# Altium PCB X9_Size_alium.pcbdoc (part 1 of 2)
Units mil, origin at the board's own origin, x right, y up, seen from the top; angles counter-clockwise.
Board outline 3938 x 2560.05 mil, 2 copper layers (TOP, BOTTOM), stack 10.4 mil thick; 72 components, 121 nets, 447 pads, 520 vias.
Unrouted connection lines stored in the file: 78.
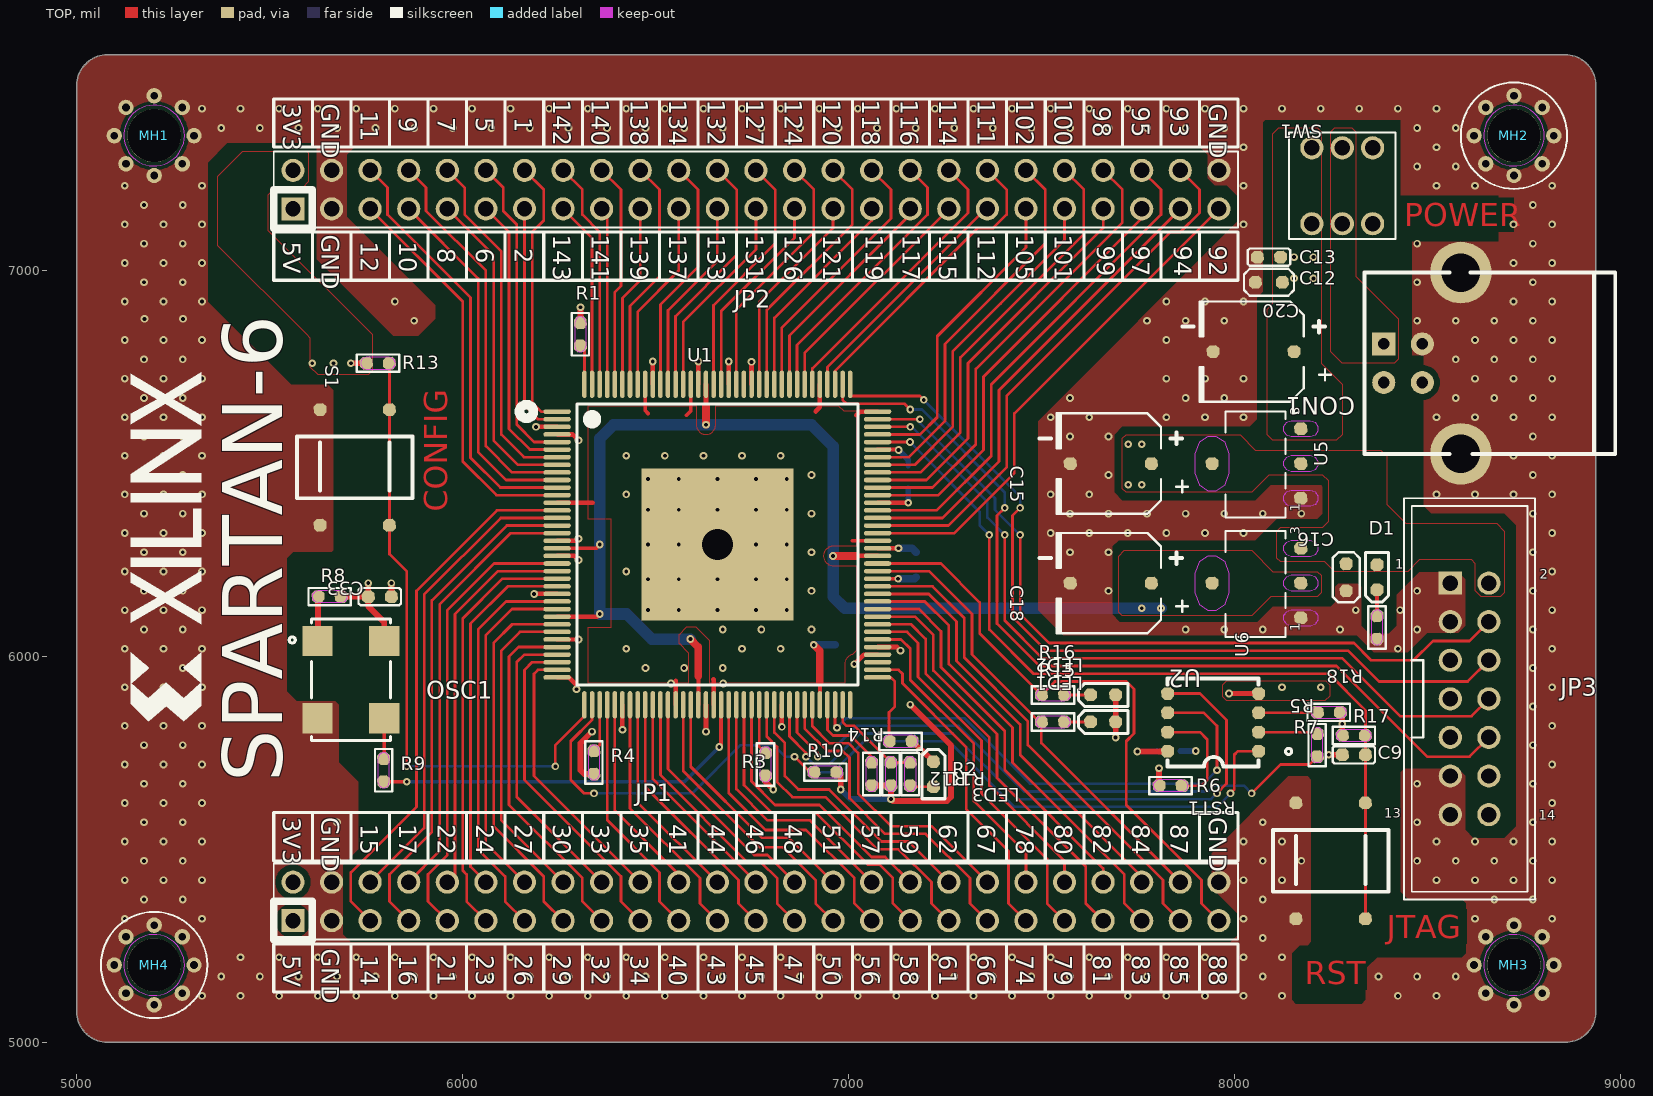
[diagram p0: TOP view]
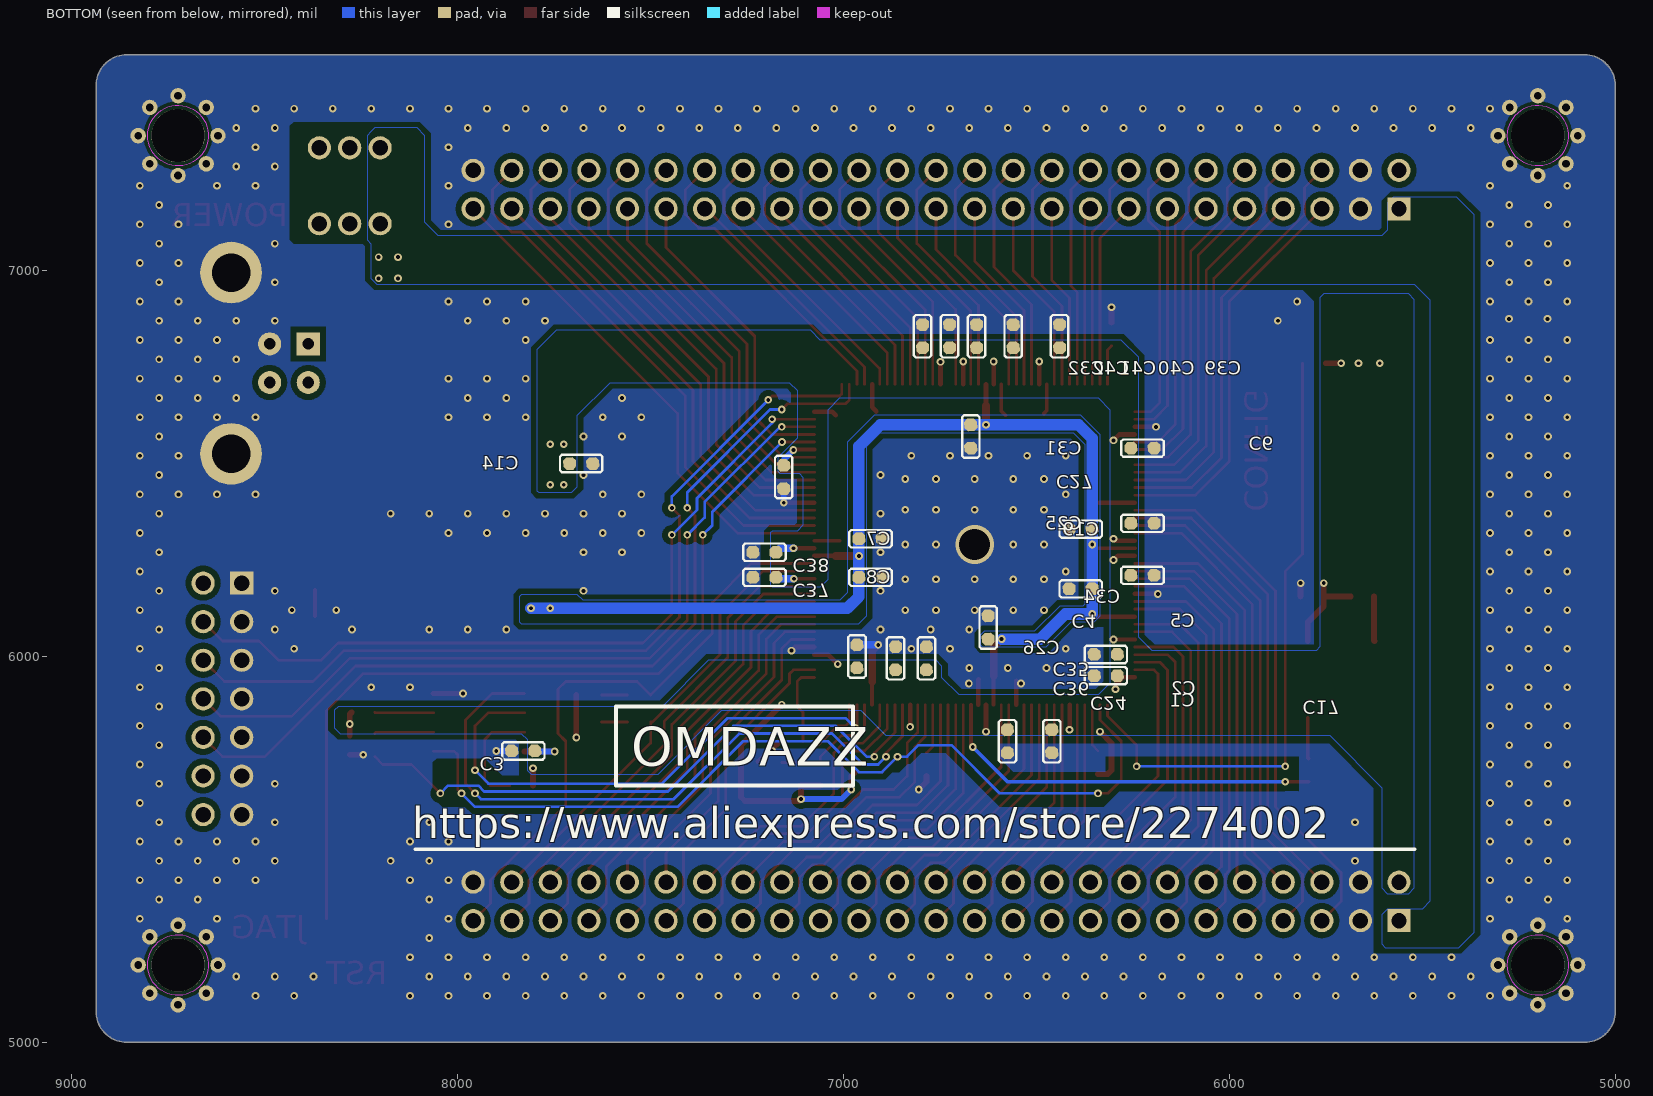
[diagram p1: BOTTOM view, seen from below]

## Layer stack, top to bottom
TOP: signal copper 1.2
Dielectric: core 8, FR-4, Dk 4.5
BOTTOM: signal copper 1.2

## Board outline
4999.5,5078.74 ccw(c5078.74,5078.74) 5078.74,4999.5 8858.26,4999.5 ccw(c8858.26,5078.74) 8937.5,5078.74 8937.5,7480.31 ccw(c8858.26,7480.31) 8858.26,7559.55 5078.74,7559.55 ccw(c5078.74,7480.31) 4999.5,7480.31

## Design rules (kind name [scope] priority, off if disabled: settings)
Clearance [All] p1: gap=10
PlaneConnect [All] p1: planeconnectstyle=Direct reliefexpansion=20 reliefentries=4 reliefconductorwidth=10 reliefairgap=10
PolygonConnect [All] p1: connectstyle=Direct reliefconductorwidth=10 reliefentries=4 polygonreliefangle="90 Angle"
RoutingVias [All] p1: holewidth=28 width=50 viastyle="Through Hole" minholewidth=28 minwidth=50 maxholewidth=28 maxwidth=50
SilkscreenOverComponentPads [All] p1: minsilkscreentomaskgap=10
SolderMaskExpansion [All] p1: expansion=4
TestPointUsage [All] p1: valid=0 allowmultiple=FALSE
Testpoint [All] p1: side=15 testpointundercomponent=TRUE minsize=40 maxsize=100 preferedsize=60 minholesize=0 maxholesize=40 preferedholesize=32 testpointgrid=1 style=1023 order=0-112345678
Width [All] p1: maxlimit=10 minlimit=10 preferedwidth=10 impedancedriven=TRUE minimp=60.000000 maximp=60.000000 favimp=60.000000
22 further rules are at their usual default settings.

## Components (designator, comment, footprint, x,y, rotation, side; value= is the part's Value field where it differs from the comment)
C1 "C0603" C0603#1 6575,5780 r90 bottom
C2 "C0603" C0603#1 6785,5995 r270 bottom
C3 "C0603" C0603#2 7830,5755 r0 bottom
C4 "C0603" C0603#2 6385,6175 r0 bottom
C5 "C0603" C0603#1 6625,6075 r90 bottom
C6 "C0603" C0603#1 6670,6570 r270 bottom
C7 "C0603" C0603#2 6930,6305 r180 bottom
C8 "C0603" C0603#2 6930,6205 r180 bottom
C9 "C0603" C0603#3 8310,5745 r0 top
C12 "C0805" C0805#1 8090,6970 r0 top
C13 "C0603" C0603#3 8090,7035 r0 top
C14 "C0603" C0603#2 7680,6500 r180 bottom
C15 "CE660X660H570" CE660X660H570 7680,6500 r180 top
C16 "C0805" C0805#2 8290,6205 r90 top
C17 "C0603" C0603#1 6460,5780 r270 bottom
C18 "CE660X660H570" CE660X660H570 7680,6190 r180 top
C19 "C0603" C0603#2 6385,6330 r180 bottom
C20 "CE660X660H570" CE660X660H570 8050,6790 r180 top
C24 "C0603" C0603#1 6865,5995 r90 bottom
C25 "C0603" C0603#2 6225,6345 r180 bottom
C26 "C0603" C0603#1 6965,6000 r90 bottom
C27 "C0603" C0603#1 7155,6465 r270 bottom
C31 "C0603" C0603#2 6225,6540 r180 bottom
C32 "C0603" C0603#1 6795,6830 r90 bottom
C33 "C0603" C0603#3 5785,6155 r180 top
C34 "C0603" C0603#2 6225,6210 r180 bottom
C35 "C0603" C0603#2 6320,6005 r0 bottom
C36 "C0603" C0603#2 6320,5950 r0 bottom
C37 "C0603" C0603#2 7205,6205 r0 bottom
C38 "C0603" C0603#2 7205,6270 r0 bottom
C39 "C0603" C0603#1 6440,6830 r90 bottom
C40 "C0603" C0603#1 6560,6830 r90 bottom
C41 "C0603" C0603#1 6655,6830 r90 bottom
C42 "C0603" C0603#1 6725,6830 r90 bottom
CON1 "USB_B_STD" USB_B_STD 8510,6760 r90 top
D1 "DIODE-0603" DIODE-0603#1 8370,6205 r270 top
JP1 "HD2X25-254_WYJ" HD2X25-254_WYJ 6760,5365 r0 top
JP2 "HD2X25-254_WYJ" HD2X25-254_WYJ 6760,7210 r0 top
JP3 "HD2X7-254_B" HD2X7-254_B 8610,5890 r270 top
LED1 "DIODE-0603" DIODE-0603#2 7660,5830 r180 top
LED2 "DIODE-0603" DIODE-0603#2 7660,5900 r180 top
LED3 "DIODE-0603" DIODE-0603#1 7220,5695 r90 top
MH1 "MH350P700_8" MH350P700_8 5200,7350 r0 top
MH2 "MH350P700_8" MH350P700_8 8725,7350 r0 top
MH3 "MH350P700_8" MH350P700_8 8725,5200 r0 top
MH4 "MH350P700_8" MH350P700_8 5200,5200 r0 top
OSC1 "OSC" OSC 5710,5940 r270 top
R1 "R0603" R0603#1 6305,6835 r270 top
R2 "R0603" R0603#1 7060,5695 r270 top
R3 "R0603" R0603#1 6785,5720 r270 top
R4 "R0603" R0603#1 6340,5725 r270 top
R5 "R0603" R0603#2 8245,5855 r180 top
R6 "R0603" R0603#2 7835,5665 r0 top
R7 "R0603" R0603#1 8215,5770 r270 top
R8 "R0603" R0603#2 5655,6155 r0 top
R9 "R0603" R0603#1 5795,5705 r270 top
R10 "R0603" R0603#2 6940,5700 r0 top
R11 "R0603" R0603#1 7160,5695 r90 top
R12 "R0603" R0603#1 7110,5695 r90 top
R13 "R0603" R0603#2 5780,6760 r0 top
R14 "R0603" R0603#2 7135,5780 r180 top
R15 "R0603" R0603#2 7530,5830 r0 top
R16 "R0603" R0603#2 7530,5900 r0 top
R17 "R0603" R0603#2 8310,5795 r0 top
R18 "R0603" R0603#1 8370,6075 r90 top
RST1 "KEY" KEY 8250,5470 r180 top
S1 "KEY" KEY 5720,6490 r180 top
SW1 "SWITCH2X3_700X700" SWITCH2X3_700X700 8280,7220 r180 top
U1 "EQFP144_EP59" EQFP144_EP59 6660,6290 r0 top
U2 "SO8" SO8 7945,5810 r180 top
U5 "SOT223_4" SOT223_4 8055,6500 r90 top
U6 "SOT223_4" SOT223_4 8055,6190 r90 top

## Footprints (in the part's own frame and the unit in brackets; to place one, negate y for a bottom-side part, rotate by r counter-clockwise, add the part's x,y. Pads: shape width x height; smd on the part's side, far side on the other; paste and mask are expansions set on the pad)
C0603#1 [mil] "C0603"
  oct 33.3x33.3 smd rot 93: 1(30,0) 2(-30,0)
  silkscreen extent -55,-23 55,23
C0603#2 [mil] "C0603"
  oct 33.3x33.3 smd rot 3: 1(30,0) 2(-30,0)
  silkscreen extent -55,-22 55,22
C0603#3 [mil] "C0603"
  oct 33.3x33.3 smd rot 3: 1(-30,0) 2(30,0)
  silkscreen extent -55,-22 55,22
C0805#1 [mil] "C0805"
  oct 33.3x33.3 smd rot 3: 1(-35,0) 2(35,0)
  silkscreen extent -65,-35 65,35
C0805#2 [mil] "C0805"
  oct 33.3x33.3 smd rot 93: 1(-35,0) 2(35,0)
  silkscreen extent -65,-35 65,35
CE660X660H570 [mil] "CE660X660H570"
  oct 33.3x33.3 smd rot 3: 1(-105,0) 2(105,0)
  silkscreen extent -200,-130 185,130
DIODE-0603#1 [mil] "DIODE-0603"
  oct 33.3x33.3 smd rot 93: A(-32.5,0) K(32.5,0)
  silkscreen extent -64,-30 64,30
DIODE-0603#2 [mil] "DIODE-0603"
  oct 33.3x33.3 smd rot 3: A(-32.5,0) K(32.5,0)
  silkscreen extent -64,-30 64,30
EQFP144_EP59 [mil] "EQFP144_EP59"
  oval 70.9x11.8 smd: 1(-415.4,344.5) 2(-415.4,324.8) 3(-415.4,305.1) 4(-415.4,285.4) 5(-415.4,265.7) 6(-415.4,246.1) 7(-415.4,226.4) 8(-415.4,206.7) 9(-415.4,187) 10(-415.4,167.3) 11(-415.4,147.6) 12(-415.4,128) 13(-415.4,108.3) 14(-415.4,88.6) 15(-415.4,68.9) 16(-415.4,49.2) 17(-415.4,29.5) 18(-415.4,9.8) 19(-415.4,-9.8) 20(-415.4,-29.5) 21(-415.4,-49.2) 22(-415.4,-68.9) 23(-415.4,-88.6) 24(-415.4,-108.3) 25(-415.4,-128) 26(-415.4,-147.6) 27(-415.4,-167.3) 28(-415.4,-187) 29(-415.4,-206.7) 30(-415.4,-226.4) 31(-415.4,-246.1) 32(-415.4,-265.7) 33(-415.4,-285.4) 34(-415.4,-305.1) 35(-415.4,-324.8) 36(-415.4,-344.5) 73(415.4,-344.5) 74(415.4,-324.8) 75(415.4,-305.1) 76(415.4,-285.4) 77(415.4,-265.7) 78(415.4,-246.1) 79(415.4,-226.4) 80(415.4,-206.7) 81(415.4,-187) 82(415.4,-167.3) 83(415.4,-147.6) 84(415.4,-128) 85(415.4,-108.3) 86(415.4,-88.6) 87(415.4,-68.9) 88(415.4,-49.2) 89(415.4,-29.5) 90(415.4,-9.8) 91(415.4,9.8) 92(415.4,29.5) 93(415.4,49.2) 94(415.4,68.9) 95(415.4,88.6) 96(415.4,108.3) 97(415.4,128) 98(415.4,147.6) 99(415.4,167.3) 100(415.4,187) 101(415.4,206.7) 102(415.4,226.4) 103(415.4,246.1) 104(415.4,265.7) 105(415.4,285.4) 106(415.4,305.1) 107(415.4,324.8) 108(415.4,344.5)
  oval 11.8x70.9 smd: 37(-344.5,-415.4) 38(-324.8,-415.4) 39(-305.1,-415.4) 40(-285.4,-415.4) 41(-265.7,-415.4) 42(-246.1,-415.4) 43(-226.4,-415.4) 44(-206.7,-415.4) 45(-187,-415.4) 46(-167.3,-415.4) 47(-147.6,-415.4) 48(-128,-415.4) 49(-108.3,-415.4) 50(-88.6,-415.4) 51(-68.9,-415.4) 52(-49.2,-415.4) 53(-29.5,-415.4) 54(-9.8,-415.4) 55(9.8,-415.4) 56(29.5,-415.4) 57(49.2,-415.4) 58(68.9,-415.4) 59(88.6,-415.4) 60(108.3,-415.4) 61(128,-415.4) 62(147.6,-415.4) 63(167.3,-415.4) 64(187,-415.4) 65(206.7,-415.4) 66(226.4,-415.4) 67(246.1,-415.4) 68(265.7,-415.4) 69(285.4,-415.4) 70(305.1,-415.4) 71(324.8,-415.4) 72(344.5,-415.4) 109(344.5,415.4) 110(324.8,415.4) 111(305.1,415.4) 112(285.4,415.4) 113(265.7,415.4) 114(246.1,415.4) 115(226.4,415.4) 116(206.7,415.4) 117(187,415.4) 118(167.3,415.4) 119(147.6,415.4) 120(128,415.4) 121(108.3,415.4) 122(88.6,415.4) 123(68.9,415.4) 124(49.2,415.4) 125(29.5,415.4) 126(9.8,415.4) 127(-9.8,415.4) 128(-29.5,415.4) 129(-49.2,415.4) 130(-68.9,415.4) 131(-88.6,415.4) 132(-108.3,415.4) 133(-128,415.4) 134(-147.6,415.4) 135(-167.3,415.4) 136(-187,415.4) 137(-206.7,415.4) 138(-226.4,415.4) 139(-246.1,415.4) 140(-265.7,415.4) 141(-285.4,415.4) 142(-305.1,415.4) 143(-324.8,415.4) 144(-344.5,415.4)
  rect 393.7x393.7 smd: EP(0,0)
  silkscreen extent -513,-364 364,364
HD2X7-254_B [mil] "HD2X7-254_B"
  rect 60x60 hole 40: 1(-300,-50)
  round 60 hole 40: 2(-300,50) 3(-200,-50) 4(-200,50) 5(-100,-50) 6(-100,50) 7(0,-50) 8(0,50) 9(100,-50) 10(100,50) 11(200,-50) 12(200,50) 13(300,-50) 14(300,50)
  silkscreen extent -520,-205 520,170
HD2X25-254_WYJ [mil] "HD2X25-254_WYJ"
  rect 60x60 hole 40: 1(-1200,-50)
  round 60 hole 40: 2(-1200,50) 3(-1100,-50) 4(-1100,50) 5(-1000,-50) 6(-1000,50) 7(-900,-50) 8(-900,50) 9(-800,-50) 10(-800,50) 11(-700,-50) 12(-700,50) 13(-600,-50) 14(-600,50) 15(-500,-50) 16(-500,50) 17(-400,-50) 18(-400,50) 19(-300,-50) 20(-300,50) 21(-200,-50) 22(-200,50) 23(-100,-50) 24(-100,50) 25(0,-50) 26(0,50) 27(100,-50) 28(100,50) 29(200,-50) 30(200,50) 31(300,-50) 32(300,50) 33(400,-50) 34(400,50) 35(500,-50) 36(500,50) 37(600,-50) 38(600,50) 39(700,-50) 40(700,50) 41(800,-50) 42(800,50) 43(900,-50) 44(900,50) 45(1000,-50) 46(1000,50) 47(1100,-50) 48(1100,50) 49(1200,-50) 50(1200,50)
  silkscreen extent -1250,-100 1250,98
KEY [mil] "KEY"
  oct 33.3x33.3 smd rot 3: 1(-90,-150) 2(-90,150) 3(90,150) 4(90,-150)
  silkscreen extent -150,-80 150,80
MH350P700_8 [mil] "MH350P700_8"
  round 138 hole 138: 1(0,0)
  round 40 hole 20: 2(0,103.35) 3(73.07,73.07) 4(103.35,0) 5(73.07,-73.07) 6(0,-103.35) 7(-73.07,-73.07) 8(-103.35,0) 9(-73.07,73.07)
  Multi-Layer keep-out circle w1: c0,0 r78.74
OSC [mil] "OSC"
  rect 78.7x78.7 smd: 1(-100,-86.6) 2(100,-86.6) 3(100,86.6) 4(-100,86.6)
  silkscreen extent -158,-160 158,102
R0603#1 [mil] "R0603"
  oct 33.3x33.3 smd rot 93: 1(-30,0) 2(30,0)
  TOP keep-out region: 45,-4 45,3.8 40,11.3 30,15 -30,15 -40,11.3 -45,3.8 -45,-3.8 -40,-11.3 -30,-15 31,-15 40,-12 45,-4
  silkscreen extent -55,-23 55,23
R0603#2 [mil] "R0603"
  oct 33.3x33.3 smd rot 3: 1(-30,0) 2(30,0)
  TOP keep-out region: 45,-4 45,3.8 40,11.3 30,15 -30,15 -40,11.3 -45,3.8 -45,-3.8 -40,-11.3 -30,-15 31,-15 40,-12 45,-4
  silkscreen extent -55,-23 55,23
SO8 [mil] "SO8"
  oct 33.3x33.3 smd rot 3: 1(-118,56.25) 2(-118,6.25) 3(-118,-43.75) 4(-118,-93.75) 5(118,-93.75) 6(118,-43.75) 7(118,6.25) 8(118,56.25)
  silkscreen extent -204,-133 118,96
SOT223_4 [mil] "SOT223_4"
  oct 33.3x33.3 smd rot 93: 1(-90,-117.5) 2(0,-117.5) 3(90,-117.5) 4(0,112.5)
  TOP keep-out region: 110.1,-142.6 110.1,-92.6 105.1,-79.3 95.1,-72.6 85.1,-72.6 75.1,-79.3 70.1,-92.6 70.1,-142.6 75.1,-155.9 85.1,-162.6 95.1,-162.6 105.1,-155.9 110.1,-142.6
  TOP keep-out region: 20.1,-142.6 20.1,-92.6 15.1,-79.3 5.1,-72.6 -4.9,-72.6 -14.9,-79.3 -19.9,-92.6 -19.9,-142.6 -14.9,-155.9 -4.9,-162.6 5.1,-162.6 15.1,-155.9 20.1,-142.6
  TOP keep-out region: 25,157.5 -25,157.5 -55,146.2 -70,123.8 -70,101.2 -55,78.8 -25,67.5 25,67.5 55,78.8 70,101.2 70,123.8 55,146.2 25,157.5
  TOP keep-out region: -70,-142.5 -70,-92.5 -75,-79.2 -85,-72.5 -95,-72.5 -105,-79.2 -110,-92.5 -110,-142.5 -105,-155.8 -95,-162.5 -85,-162.5 -75,-155.8 -70,-142.5
  silkscreen extent -140,-208 135,78
SWITCH2X3_700X700 [mil] "SWITCH2X3_700X700"
  round 60 hole 40: 1(-78.74,-98.43) 2(0,-98.43) 3(78.74,-98.43) 4(-78.74,98.43) 5(0,98.43) 6(78.74,98.43)
  silkscreen extent -138,-138 138,138
USB_B_STD [mil] "USB_B_STD"
  rect 60x60 hole 30: 1(50,122.5)
  round 60 hole 30: 2(-50,122.5) 3(-50,22.5) 4(50,22.5)
  round 160 hole 100: 5(235,-77.5) 6(-235,-77.5)
  silkscreen extent -235,-478 235,173

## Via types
v1: diameter 20, hole 10, TOP to BOTTOM, 519 vias
v2: diameter 100, hole 80, TOP to BOTTOM, 1 vias

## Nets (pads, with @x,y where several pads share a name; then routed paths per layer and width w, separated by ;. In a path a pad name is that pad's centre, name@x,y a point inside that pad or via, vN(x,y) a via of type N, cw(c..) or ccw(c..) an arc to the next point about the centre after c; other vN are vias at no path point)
1: JP2.14 U1.1 | length 709.5
  TOP w7: JP2.14@6160,7260 6210,7210 6210,7130 6180,7100 6180,6657.87 6203.37,6634.5 U1.1@6244.6,6634.5
2: JP2.13 U1.2 | length 609.2
  TOP w7: JP2.13@6160,7160 6160,6650 6195.2,6614.8 U1.2@6244.6,6614.8
5: JP2.12 U1.5 | length 815.7
  TOP w7: JP2.12@6060,7260 6105,7215 6105,7155 6140,7120 6140,6600.7 6185,6555.7 U1.5@6244.6,6555.7
6: JP2.11 U1.6 | length 741.8
  TOP w7: JP2.11@6060,7160 6120,7100 6120,6590 6173.9,6536.1 U1.6@6244.6,6536.1
7: JP2.10 U1.7 | length 911.9
  TOP w7: JP2.10@5960,7260 6005,7215 6005,7145 6100,7050 6100,6575 6158.6,6516.4 U1.7@6244.6,6516.4
8: JP2.9 U1.8 | length 840.5
  TOP w7: JP2.9@5960,7160 6080,7040 6080,6560 6143.3,6496.7 U1.8@6244.6,6496.7
9: JP2.8 U1.9 | length 1010.6
  TOP w7: JP2.8@5860,7260 5905,7215 5905,7155 6060,7000 6060,6545 6128,6477 U1.9@6244.6,6477
10: JP2.7 U1.10 | length 939.3
  TOP w7: JP2.7@5860,7160 6040,6980 6040,6530 6112.7,6457.3 U1.10@6244.6,6457.3
11: JP2.6 U1.11 | length 1109.4
  TOP w7: JP2.6@5760,7260 5805,7215 5805,7145 6020,6930 6020,6515 6097.4,6437.6 U1.11@6244.6,6437.6
12: JP2.5 U1.12 | length 1035
  TOP w7: JP2.5@5760,7160 6000,6920 6000,6505 6087,6418 U1.12@6244.6,6418
14: JP1.5 U1.14 | length 1397.1
  TOP w7: JP1.5@5760,5315 5710,5365 5710,5440 5880,5610 5880,6170 6088.6,6378.6 U1.14@6244.6,6378.6
15: JP1.6 U1.15 | length 1230
  TOP w7: JP1.6@5760,5415 5900,5555 5900,6160 6098.9,6358.9 U1.15@6244.6,6358.9
16: JP1.7 U1.16 | length 1301.3
  TOP w7: JP1.7@5860,5315 5810,5365 5810,5435 5920,5545 5920,6145 6114.2,6339.2 U1.16@6244.6,6339.2
17: JP1.8 U1.17 | length 1134.2
  TOP w7: JP1.8@5860,5415 5940,5495 5940,6135 6124.5,6319.5 U1.17@6244.6,6319.5
21: JP1.9 U1.21 | length 1181.1
  TOP w7: JP1.9@5960,5315 5910,5365 5910,5435 5960,5485 5960,6120 6080.8,6240.8 U1.21@6244.6,6240.8
22: JP1.10 U1.22 | length 1013.9
  TOP w7: JP1.10@5960,5415 5980,5435 5980,6110 6091.1,6221.1 U1.22@6244.6,6221.1
23: JP1.11 U1.23 | length 1095.2
  TOP w7: JP1.11@6060,5315 6010,5365 6010,5435 6000,5445 6000,6097.87 6103.53,6201.4 U1.23@6244.6,6201.4
24: JP1.12 U1.24 | length 951.2
  TOP w7: JP1.12@6060,5415 6020,5455 6020,6085 6116.7,6181.7 U1.24@6244.6,6181.7
26: JP1.13 U1.26 | length 1039.3
  TOP w7: JP1.13@6160,5315 6110,5365 6110,5430 6040,5500 6040,6070 6112.4,6142.4 U1.26@6244.6,6142.4
27: JP1.14 U1.27 | length 894.1
  TOP w7: JP1.14@6160,5415 6060,5515 6060,6055 6127.7,6122.7 U1.27@6244.6,6122.7
29: JP1.15 U1.29 | length 979.2
  TOP w7: U1.29@6244.6,6083.3 6128.3,6083.3 6080,6035 6080,5560 6210,5430 6210,5365 JP1.15@6260,5315
30: JP1.16 U1.30 | length 831
  TOP w7: U1.30@6244.6,6063.6 6148.6,6063.6 6100,6015 6100,5575 JP1.16@6260,5415
32: JP1.17 U1.32 | length 919.1
  TOP w7: U1.32@6244.6,6024.3 6144.3,6024.3 6120,6000 6120,5615 6310,5425 6310,5365 JP1.17@6360,5315
33: JP1.18 U1.33 | length 773.8
  TOP w7: U1.33@6244.6,6004.6 6159.6,6004.6 6140,5985 6140,5635 JP1.18@6360,5415
34: JP1.19 U1.34 | length 867.1
  TOP w7: U1.34@6244.6,5984.9 6179.9,5984.9 6160,5965 6160,5680 6410,5430 6410,5365 JP1.19@6460,5315
35: JP1.20 U1.35 | length 717.9
  TOP w7: U1.35@6244.6,5965.2 6195.2,5965.2 6184.74,5954.74 6184.74,5690.26 JP1.20@6460,5415
40: JP1.21 U1.40 | length 636.4
  TOP w7: U1.40@6374.6,5874.6 6374.6,5575.4 6510,5440 6510,5365 JP1.21@6560,5315
41: JP1.22 U1.41 | length 528.2
  TOP w7: U1.41@6394.3,5874.6 6394.3,5600.7 6560,5435 JP1.22@6560,5415
43: JP1.23 U1.43 | length 653.4
  TOP w7: U1.43@6433.6,5874.6 6433.7,5874.5 6433.7,5606.3 6615,5425 6615,5360 JP1.23@6660,5315
44: JP1.24 U1.44 | length 545.2
  TOP w7: U1.44@6453.3,5874.6 6453.3,5621.7 JP1.24@6660,5415
45: JP1.25 U1.45 | length 678.5
  TOP w7: U1.45@6473,5874.6 6473.1,5874.5 6473.1,5661.9 6715,5420 6715,5360 JP1.25@6760,5315
46: JP1.26 U1.46 | length 570.3
  TOP w7: U1.46@6492.7,5874.6 6492.7,5682.3 JP1.26@6760,5415
47: JP1.27 U1.47 | length 724.1
  TOP w7: U1.47@6512.4,5874.6 6512.4,5692.6 6740,5465 6775,5465 6815,5425 6815,5360 JP1.27@6860,5315
48: JP1.28 U1.48 | length 616
  TOP w7: U1.48@6532,5874.6 6532,5708 6755,5485 6790,5485 JP1.28@6860,5415
50: JP1.29 U1.50 | length 755.7
  TOP w7: U1.50@6571.4,5874.6 6571.4,5703.6 6770,5505 6830,5505 6915,5420 6915,5360 JP1.29@6960,5315
51: JP1.30 U1.51 | length 653.4
  TOP w7: U1.51@6591.1,5874.6 6591.1,5713.9 6775,5530 6845,5530 JP1.30@6960,5415
56: JP1.31 U1.56 | length 774.6
  TOP w7: U1.56@6689.5,5874.6 6689.5,5645.5 6785,5550 6890,5550 7015,5425 7015,5360 JP1.31@7060,5315
57: JP1.32 U1.57 | length 669.3
  TOP w7: U1.57@6709.2,5874.6 6709.2,5655.8 6790,5575 6900,5575 JP1.32@7060,5415
58: JP1.33 U1.58 | length 823.1
  TOP w7: U1.58@6728.9,5874.6 6728.9,5666.1 6800,5595 6915,5595 7050,5460 7080,5460 7115,5425 7115,5360 JP1.33@7160,5315
59: JP1.34 U1.59 | length 717.9
  TOP w7: U1.59@6748.6,5874.6 6748.6,5676.4 6810,5615 6925,5615 7060,5480 7095,5480 JP1.34@7160,5415
61: JP1.35 U1.61 | length 837.1
  TOP w7: U1.61@6788,5874.6 6788,5792 6815,5765 6815,5675 6855,5635 6940,5635 7075,5500 7130,5500 7215,5415 7215,5360 JP1.35@7260,5315
62: JP1.36 U1.62 | length 734.9
  TOP w7: U1.62@6807.6,5874.6 6807.6,5802.4 6835,5775 6835,5690 6870,5655 6950,5655 7085,5520 7155,5520 JP1.36@7260,5415
66: JP1.37 U1.66 | length 840.7
  TOP w7: U1.66@6886.4,5874.6 6886.4,5813.6 6945,5755 6985,5755 7002.5,5737.5 7002.5,5632.5 7095,5540 7200,5540 7315,5425 7315,5360 JP1.37@7360,5315
67: JP1.38 U1.67 | length 738.4
  TOP w7: U1.67@6906.1,5874.6 6906.1,5818.9 6950,5775 7000,5775 7025,5750 7025,5645 7110,5560 7215,5560 JP1.38@7360,5415
74: JP1.39 U1.74 | length 841.4
  TOP w7: U1.74@7075.4,5965.2 7129.8,5965.2 7140,5955 7140,5930.39 7305,5765.39 7305,5605 7415,5495 7415,5360 JP1.39@7460,5315
78: JP1.40 U1.78 | length 823.8
  TOP w7: U1.78@7075.4,6043.9 7136.1,6043.9 7160,6020 7160,5938.68 7325,5773.68 7325,5625 7460,5490 JP1.40@7460,5415
79: JP1.41 U1.79 | length 993.8
  TOP w7: U1.79@7075.4,6063.6 7151.4,6063.6 7180,6035 7180,5946.97 7345,5781.97 7345,5645 7515,5475 7515,5360 JP1.41@7560,5315
80: JP1.42 U1.80 | length 919.6
  TOP w7: U1.80@7075.4,6083.3 7161.7,6083.3 7200,6045 7200,5955.26 7365,5790.26 7365,5665 7560,5470 JP1.42@7560,5415
81: JP1.43 U1.81 | length 1086.7
  TOP w7: U1.81@7075.4,6103 7172,6103 7220,6055 7220,5963.55 7385,5798.55 7385,5685 7615,5455 7615,5360 JP1.43@7660,5315
82: JP1.44 U1.82 | length 1012.5
  TOP w7: U1.82@7075.4,6122.7 7182.3,6122.7 7240,6065 7240,5971.84 7405,5806.84 7405,5705 7660,5450 JP1.44@7660,5415
83: JP1.45 U1.83 | length 1182.6
  TOP w7: U1.83@7075.4,6142.4 7197.6,6142.4 7260,6080 7260,5980.13 7425,5815.13 7425,5725 7715,5435 7715,5360 JP1.45@7760,5315
84: JP1.46 U1.84 | length 1108.2
  TOP w7: U1.84@7075.4,6162 7208,6162 7280,6090 7280,5988.42 7445,5823.42 7445,5745 7760,5430 JP1.46@7760,5415
85: JP1.47 U1.85 | length 1275.4
  TOP w7: U1.85@7075.4,6181.7 7218.3,6181.7 7300,6100 7300,5996.71 7465,5831.71 7465,5770 7815,5420 7815,5360 JP1.47@7860,5315
87: JP1.48 R15.1 U1.87 | length 1212.2
  TOP w7: U1.87@7075.4,6221.1 7208.9,6221.1 7320,6110 7320,6005 7495,5830 R15.1@7500,5830 7500,5775 JP1.48@7860,5415
88: JP1.49 R16.1 U1.88 | length 1583.1
  TOP w7: U1.88@7075.4,6240.8 7239.2,6240.8 7340,6140 7340,6060 R16.1@7500,5900 7535,5935 7720,5935 7740,5915 7740,5800 7720,5780 7720,5615 7915,5420 7915,5360 JP1.49@7960,5315
92: JP2.49 U1.92 | length 1323.5
  TOP w7: U1.92@7075.4,6319.5 7274.5,6319.5 7430,6475 7430,6630 JP2.49@7960,7160
93: JP2.48 U1.93 | length 1409.5
  TOP w7: U1.93@7075.4,6339.2 7259.2,6339.2 7410,6490 7410,6675 7835,7100 7860,7100 7910,7150 7910,7210 JP2.48@7860,7260
94: JP2.47 U1.94 | length 1224.8
  TOP w7: U1.94@7075.4,6358.9 7243.9,6358.9 7390,6505 7390,6690 JP2.47@7860,7160
95: JP2.46 U1.95 | length 1296.1
  TOP w7: U1.95@7075.4,6378.6 7228.6,6378.6 7370,6520 7370,6705 7810,7145 7810,7210 JP2.46@7760,7260
97: JP2.45 U1.97 | length 1117.9
  TOP w7: U1.97@7075.4,6418 7233,6418 7350,6535 7350,6725 7760,7135 JP2.45@7760,7160
98: JP2.44 U1.98 | length 1189.3
  TOP w7: U1.98@7075.4,6437.6 7217.6,6437.6 7330,6550 7330,6745 7710,7125 7710,7210 JP2.44@7660,7260
99: JP2.43 U1.99 | length 1019.2
  TOP w7: U1.99@7075.4,6457.3 7202.3,6457.3 7310,6565 7310,6760 7660,7110 JP2.43@7660,7160
100: JP2.42 U1.100 | length 1090.5
  TOP w7: U1.100@7075.4,6477 7187,6477 7290,6580 7290,6775 7610,7095 7610,7210 JP2.42@7560,7260
101: JP2.41 U1.101 | length 920.9
  TOP w7: U1.101@7075.4,6496.7 7171.7,6496.7 7270,6595 7270,6790.8 7393.63,6914.43 7394.43,6914.43 7560,7080 JP2.41@7560,7160
102: JP2.40 U1.102 | length 991.8
  TOP w7: U1.102@7075.4,6516.4 7156.4,6516.4 7250,6610 7250,6810 7510,7070 7510,7210 JP2.40@7460,7260
105: JP2.39 U1.105 | length 808.3
  TOP w7: U1.105@7075.4,6575.4 7185.4,6575.4 7230,6620 7230,6830 7460,7060 JP2.39@7460,7160
111: JP2.38 U1.111 | length 783
  TOP w7: U1.111@6965.1,6705.4 6965.1,6740.1 7335,7110 7375,7110 7410,7145 7410,7210 JP2.38@7360,7260
112: JP2.37 U1.112 | length 629.3
  TOP w7: U1.112@6945.4,6705.4 6945.4,6750.4 7355,7160 JP2.37@7360,7160
114: JP2.36 U1.114 | length 742.6
  TOP w7: U1.114@6906.1,6705.4 6906.1,6746.1 7310,7150 7310,7210 JP2.36@7260,7260
115: JP2.35 U1.115 | length 609.4
  TOP w7: U1.115@6886.4,6705.4 6886.4,6786.4 JP2.35@7260,7160
116: JP2.34 U1.116 | length 713.4
  TOP w7: U1.116@6866.7,6705.4 6866.7,6806.7 7205,7145 7205,7215 JP2.34@7160,7260
117: JP2.33 U1.117 | length 584.2
  TOP w7: U1.117@6847,6705.4 6847,6832 7160,7145 JP2.33@7160,7160
118: JP2.32 U1.118 | length 692.4
  TOP w7: U1.118@6827.3,6705.4 6827.3,6852.3 7110,7135 7110,7210 JP2.32@7060,7260
119: JP2.31 U1.119 | length 559.1
  TOP w7: U1.119@6807.6,6705.4 6807.6,6877.6 7060,7130 JP2.31@7060,7160
120: JP2.30 U1.120 | length 667.3
  TOP w7: U1.120@6788,6705.4 6788,6898 7010,7120 7010,7210 JP2.30@6960,7260
121: JP2.29 U1.121 | length 534
  TOP w7: U1.121@6768.3,6705.4 6768.3,6918.3 6960,7110 JP2.29@6960,7160
124: JP2.28 U1.124 | length 658.5
  TOP w7: U1.124@6709.2,6705.4 6709.2,6899.2 6910,7100 6910,7210 JP2.28@6860,7260
126: JP2.27 U1.126 | length 533.4
  TOP w7: U1.126@6669.8,6705.4 6669.8,6894.8 6860,7085 JP2.27@6860,7160
127: JP2.26 U1.127 | length 641.5
  TOP w7: U1.127@6650.2,6705.4 6650.2,6910.2 6810,7070 6810,7210 JP2.26@6760,7260
131: JP2.25 U1.131 | length 532.7
  TOP w7: U1.131@6571.4,6705.4 6571.4,6866.4 6760,7055 JP2.25@6760,7160
132: JP2.24 U1.132 | length 640.9
  TOP w7: U1.132@6551.7,6705.4 6551.7,6881.7 6710,7040 6710,7210 JP2.24@6660,7260
133: JP2.23 U1.133 | length 507.6
  TOP w7: U1.133@6532,6705.4 6532,6897 6660,7025 JP2.23@6660,7160
134: JP2.22 U1.134 | length 615.7
  TOP w7: U1.134@6512.4,6705.4 6512.4,6912.4 6610,7010 6610,7210 JP2.22@6560,7260
137: JP2.21 U1.137 | length 498.8
  TOP w7: U1.137@6453.3,6705.4 6453.3,6893.3 6560,7000 JP2.21@6560,7160
138: JP2.20 U1.138 | length 607
  TOP w7: U1.138@6433.6,6705.4 6433.6,6908.6 6510,6985 6510,7210 JP2.20@6460,7260
139: JP2.19 U1.139 | length 473.7
  TOP w7: U1.139@6413.9,6705.4 6413.9,6928.9 6460,6975 JP2.19@6460,7160
140: JP2.18 U1.140 | length 581.8
  TOP w7: JP2.18@6360,7260 6410,7210 6410,6960 6394.3,6944.3 U1.140@6394.3,6705.4
141: JP2.17 U1.141 | length 460.6
  TOP w7: JP2.17@6360,7160 6374.6,7145.4 U1.141@6374.6,6705.4
142: JP2.16 U1.142 | length 593.9
  TOP w7: JP2.16@6260,7260 6310,7210 6310,7145 6354.9,7100.1 U1.142@6354.9,6705.4
143: JP2.15 U1.143 | length 485.7
  TOP w7: JP2.15@6260,7160 6335.2,7084.8 U1.143@6335.2,6705.4
144: R1.2 U1.144 | length 103.9
  TOP w7: R1.2@6305,6805 6315.5,6794.5 U1.144@6315.5,6705.4
CLK0: R9.2 U1.55 | length 1018.9
  TOP w10: R9.2@5795,5675 v1(5855,5675) ; v1(6665,5765) 6669.8,5769.8 U1.55@6669.8,5874.6
  BOTTOM w10: v1(5855,5675) 6575,5675 v1(6665,5765)
CSO_B: R10.1 U1.38 U2.1 | length 2378.1
  TOP w7: U1.38@6335.2,5874.6 6335.2,5835.2 6280,5780 6280,5680 6315,5645 v1(6340,5645) ; v1(6860,5740) 6900,5700 R10.1@6910,5700 ; v1(7990,5645) 8000,5655 8000,5745 8008.75,5753.75 U2.1@8063,5753.75
  BOTTOM w7: v1(6340,5645) 6595,5645 6720,5770 6805,5770 6835,5740 v1(6860,5740) 6900,5700 6960,5700 7040,5780 7260,5780 7430,5610 7955,5610 v1(7990,5645)
DONE: R11.2 R12.2 U1.71 | length 263.2
  TOP w7: U1.71@6984.8,5874.6 6984.8,5830.2 6995,5820 7015,5820 R12.2@7110,5725 R11.2@7160,5725
FPGA_1V2: C4.2 C5.2 C6.2 C7.2 C8.2 C18.1 C19.1 U1.19 U1.28 U1.52 U1.89 U1.128 U6.2 U6.4 | length 3239.4
  TOP w10: U1.19@6244.6,6280.2 6345.2,6280.2 v1(6355,6290) ; U1.52@6610.8,5874.6 6610.8,5949.2
  TOP w12: U1.28@6244.6,6103 6348,6103 v1(6355,6110) ; 6630.5,6650 U1.128@6630.5,6705.4 ; 7020,6260.5 U1.89@7075.4,6260.5
  TOP w20: v1(6590,6045) 6610.8,6024.2 6610.8,5949.2 ; v1(6630.5,6600.5) 6630.5,6650 ; v1(6960,6260.5) 7020,6260.5
  BOTTOM w20: v1@6630,6600 v1(6630.5,6600.5)
  BOTTOM w30: v1(6590,6045) 6490,6045 6425,6110 v1(6355,6110) C4.2@6355,6175 v1(6355,6290) C19.1@6355,6330 6355,6565 6390,6600 6630,6600 C6.2@6670,6600 6905,6600 6960,6545 C7.2@6960,6305 v1(6960,6260.5) C8.2@6960,6205 6960,6155 6990,6125 v1(7760,6125) v1(7810,6125)
FPGA_3V3: C1.1 C2.1 C3.2 C14.2 C15.1 C16.2 C17.2 C24.2 C25.2 C26.2 C27.2 C31.2 C32.2 C33.2 C34.2 C35.2 C36.2 C37.2 C38.2 C39.2 C40.2 C41.2 C42.2 D1.A JP1.2 JP2.2 JP3.2 LED1.A LED2.A OSC1.4 R2.2 R4.2 R5.1 R6.1 R8.2 R10.2 R12.1 R13.1 R17.1 U1.4 U1.18 U1.20 U1.31 U1.36 U1.42 U1.53 U1.63 U1.76 U1.86 U1.90 U1.103 U1.122 U1.125 U1.129 U1.135 U2.8 U5.2 U5.4 U6.3 | length 2606.9
  TOP w10: U1.31@6244.6,6043.9 v1(6300,6043.9) ; U1.86@7075.4,6201.4 v1(7128.6,6201.4) ; U1.103@7075.4,6536.1 7128.9,6536.1 v1(7130,6535)
  TOP w12: U1.36@6244.6,5945.5 6274.5,5945.5 6295,5925 v1(6295,5915) ; U1.20@6244.6,6260.5 6289.5,6260.5 v1(6300,6250) ; U1.18@6244.6,6299.8 6294.8,6299.8 v1(6300,6305) ; U1.4@6244.6,6575.4 6284.6,6575.4 v1(6300,6560) ; v1(6413.9,5810) U1.42@6413.9,5874.6 ; U1.135@6492.7,6705.4 v1(6492.7,6764.5) ; U1.129@6610.8,6705.4 v1(6610.8,6764.5) ; v1(6630.5,5805) U1.53@6630.5,5874.6 ; U1.125@6689.5,6705.4 v1(6689.5,6764.5) ; U1.122@6748.6,6705.4 v1(6748.6,6763.6) ; v1(6827.3,5817.3) U1.63@6827.3,5874.6 ; v1(7015,5980) 7039.6,6004.6 U1.76@7075.4,6004.6 ; U1.90@7075.4,6280.2 v1(7129.8,6280.2)
  TOP w15: R8.2@5685,6155 C33.2@5755,6155 ; v1(5710,6760) R13.1@5750,6760 ; v1(5755,6190) C33.2@5755,6155 ; OSC1.4@5796.6,6040 5796.6,6088.4 5755,6130 C33.2@5755,6155 ; v1(6335,5805) 6305,5775 6305,5705 6315,5695 R4.2@6340,5695 ; R10.2@6970,5700 6980,5690 v1(6980,5655) ; R2.2@7060,5665 R12.1@7110,5665 v1(7110,5630) 7115,5625 7255,5625 7265.61,5635.61 7265.61,5769.39 v1(7160,5875) ; v1(7692.5,5790) LED1.A@7692.5,5830 LED2.A@7692.5,5900 ; v1(7748.75,5753.75) U2.8@7827,5753.75 ; R6.1@7805,5665 v1(7805,5710) ; R5.1@8275,5855 8280,5850 v1(8280,5825) R17.1@8280,5795
  BOTTOM w15: v1(6980,5655) 7005,5630 v1(7110,5630) ; v1(7130,6535) 7155,6510 C27.2@7155,6495 ; v1(7748.75,5753.75) 7798.75,5753.75 C3.2@7800,5755
  BOTTOM w20: v1(7128.6,6201.4) 7171.4,6201.4 C37.2@7175,6205 ; v1(7129.8,6280.2) 7164.8,6280.2 C38.2@7175,6270
  other v1: 7725,6445 7760,6445 7725,6550 7760,6550 5610,6760 5665,6760
FPGA_CLK: U1.70 U2.6 | length 1398.9
  TOP w7: U1.70@6965.1,5874.6 6965.1,5819.9 v1(6970,5815) ; U2.6@7827,5853.75 7921.25,5853.75 7955,5820 v1(7955,5705)
  BOTTOM w7: v1(6970,5815) 6995,5840 7300,5840 7470,5670 7920,5670 v1(7955,5705)
FPGA_DIN: R7.2 U1.65 | length 1609.1
  TOP w7: U1.65@6866.7,5874.6 6866.7,5803.3 6920,5750 v1(6920,5740) ; v1(8045,5645) 8120,5720 8195,5720 R7.2@8215,5740
  BOTTOM w7: v1(6920,5740) 6940,5740 7020,5820 7285,5820 7455,5650 7931.71,5650 7946.71,5665 8025,5665 v1(8045,5645)
FPGA_MISO: R7.1 U2.2 | length 153.6
  TOP w7: U2.2@8063,5803.75 8211.25,5803.75 R7.1@8215,5800
FPGA_MOSI: U1.64 U2.5 | length 1717.3
  TOP w7: U1.64@6847,5874.6 6847,5793 6890,5750 v1(6890,5740) ; U2.5@7827,5903.75 7911.25,5903.75 7980,5835 7980,5670 v1(7955,5645)
  BOTTOM w7: v1(6890,5740) 6910,5720 6950,5720 7030,5800 7270,5800 7440,5630 7940,5630 v1(7955,5645)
